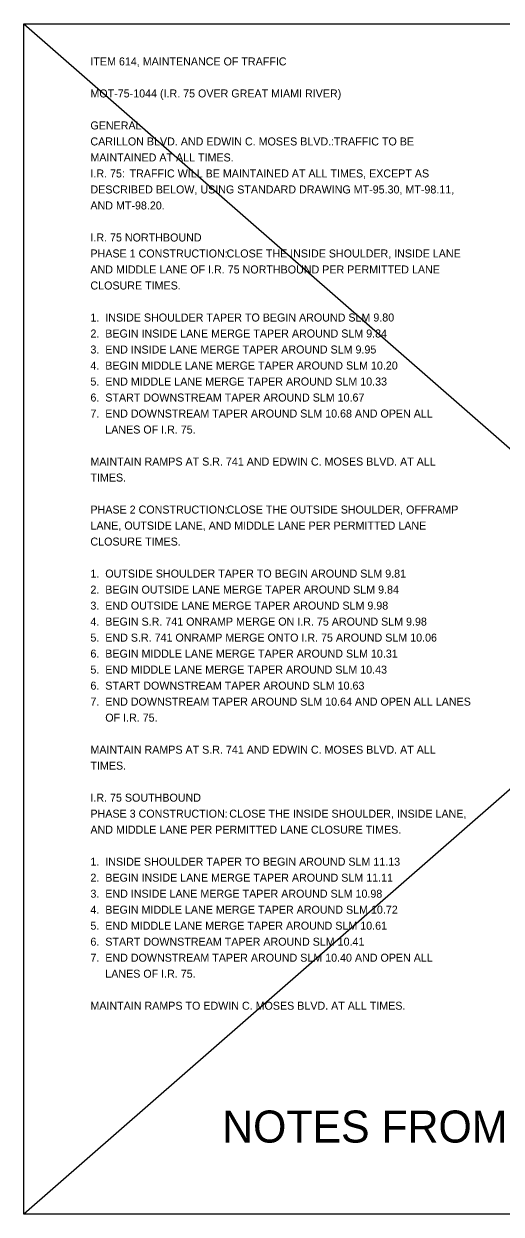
# Model space of a CAD drawing. Extents: x -25.5 to 52.6, y -2.3 to 22.
# Drawn here: x -25.52 to -17.16, y 0.89 to 21.72 of the extents above; entities that cross this region are included whole.
import ezdxf

# ---------------------------------------------------------------- set-up
doc = ezdxf.new("R2010")
doc.units = 0
doc.layers.add('Default', color=7, linetype='Continuous')
doc.layers.add('SH_Text', color=7, linetype='Continuous')

msp = doc.modelspace()

# ---------------------------------------------------------------- linework, layer by layer
at = {"layer": 'Default'}
msp.add_lwpolyline([(-25.517, 21.716), (-1.676, 21.716), (-1.676, 0.891), (-25.517, 0.891)], close=True, dxfattribs=at)
at = {"layer": 'SH_Text'}
for p, q in [((-25.517, 21.716), (-1.676, 0.891)), ((-1.676, 21.716), (-25.517, 0.891))]:
    msp.add_line(p, q, dxfattribs=at)

# ---------------------------------------------------------------- texts
for s, height, p in [('ITEM 614, MAINTENANCE OF TRAFFIC', 0.14, (-24.351, 20.988)), ('MOT-75-1044 (I.R. 75 OVER GREAT MIAMI RIVER)', 0.14, (-24.351, 20.428)), ('GENERAL', 0.14, (-24.351, 19.868)), ('CARILLON BLVD. AND EDWIN C. MOSES BLVD.: ', 0.14, (-24.351, 19.588)), ('TRAFFIC TO BE ', 0.14, (-20.091, 19.588)), ('MAINTAINED AT ALL TIMES.', 0.14, (-24.351, 19.308)), ('I.R. 75: ', 0.14, (-24.351, 19.028)), ('TRAFFIC WILL BE MAINTAINED AT ALL TIMES, EXCEPT AS ', 0.14, (-23.666, 19.028)), ('DESCRIBED BELOW, USING STANDARD DRAWING MT-95.30, MT-98.11, ', 0.14, (-24.351, 18.748)), ('AND MT-98.20.', 0.14, (-24.351, 18.468)), ('I.R. 75 NORTHBOUND', 0.14, (-24.351, 17.908)), ('PHASE 1 CONSTRUCTION:', 0.14, (-24.351, 17.628)), (' CLOSE THE INSIDE SHOULDER, INSIDE LANE ', 0.14, (-22.02, 17.628)), ('AND MIDDLE LANE OF I.R. 75 NORTHBOUND PER PERMITTED LANE ', 0.14, (-24.351, 17.348)), ('CLOSURE TIMES.', 0.14, (-24.351, 17.068)), ('1.  INSIDE SHOULDER TAPER TO BEGIN AROUND SLM 9.80', 0.14, (-24.351, 16.508)), ('2.  BEGIN INSIDE LANE MERGE TAPER AROUND SLM 9.84', 0.14, (-24.351, 16.228)), ('3.  END INSIDE LANE MERGE TAPER AROUND SLM 9.95', 0.14, (-24.351, 15.948)), ('4.  BEGIN MIDDLE LANE MERGE TAPER AROUND SLM 10.20', 0.14, (-24.351, 15.668)), ('5.  END MIDDLE LANE MERGE TAPER AROUND SLM 10.33', 0.14, (-24.351, 15.388)), ('6.  START DOWNSTREAM TAPER AROUND SLM 10.67', 0.14, (-24.351, 15.108)), ('7.  END DOWNSTREAM TAPER AROUND SLM 10.68 AND OPEN ALL', 0.14, (-24.351, 14.828)), ('     LANES OF I.R. 75.', 0.14, (-24.351, 14.548)), ('MAINTAIN RAMPS AT S.R. 741 AND EDWIN C. MOSES BLVD. AT ALL ', 0.14, (-24.351, 13.988)), ('TIMES.', 0.14, (-24.351, 13.708)), ('PHASE 2 CONSTRUCTION:', 0.14, (-24.351, 13.148)), (' CLOSE THE OUTSIDE SHOULDER, OFFRAMP ', 0.14, (-22.02, 13.148)), ('LANE, OUTSIDE LANE, AND MIDDLE LANE PER PERMITTED LANE ', 0.14, (-24.351, 12.868)), ('CLOSURE TIMES.', 0.14, (-24.351, 12.588)), ('1.  OUTSIDE SHOULDER TAPER TO BEGIN AROUND SLM 9.81', 0.14, (-24.351, 12.028)), ('2.  BEGIN OUTSIDE LANE MERGE TAPER AROUND SLM 9.84', 0.14, (-24.351, 11.748)), ('3.  END OUTSIDE LANE MERGE TAPER AROUND SLM 9.98', 0.14, (-24.351, 11.468)), ('4.  BEGIN S.R. 741 ONRAMP MERGE ON I.R. 75 AROUND SLM 9.98', 0.14, (-24.351, 11.188)), ('5.  END S.R. 741 ONRAMP MERGE ONTO I.R. 75 AROUND SLM 10.06', 0.14, (-24.351, 10.908)), ('6.  BEGIN MIDDLE LANE MERGE TAPER AROUND SLM 10.31', 0.14, (-24.351, 10.628)), ('5.  END MIDDLE LANE MERGE TAPER AROUND SLM 10.43', 0.14, (-24.351, 10.348)), ('6.  START DOWNSTREAM TAPER AROUND SLM 10.63', 0.14, (-24.351, 10.068)), ('7.  END DOWNSTREAM TAPER AROUND SLM 10.64 AND OPEN ALL LANES', 0.14, (-24.351, 9.788)), ('     OF I.R. 75.', 0.14, (-24.351, 9.508)), ('MAINTAIN RAMPS AT S.R. 741 AND EDWIN C. MOSES BLVD. AT ALL ', 0.14, (-24.351, 8.948)), ('TIMES.', 0.14, (-24.351, 8.668)), ('I.R. 75 SOUTHBOUND', 0.14, (-24.351, 8.108)), ('PHASE 3 CONSTRUCTION:  ', 0.14, (-24.351, 7.828)), ('CLOSE THE INSIDE SHOULDER, INSIDE LANE, ', 0.14, (-21.921, 7.828)), ('AND MIDDLE LANE PER PERMITTED LANE CLOSURE TIMES.', 0.14, (-24.351, 7.548)), ('1.  INSIDE SHOULDER TAPER TO BEGIN AROUND SLM 11.13', 0.14, (-24.351, 6.988)), ('2.  BEGIN INSIDE LANE MERGE TAPER AROUND SLM 11.11', 0.14, (-24.351, 6.708)), ('3.  END INSIDE LANE MERGE TAPER AROUND SLM 10.98', 0.14, (-24.351, 6.428)), ('4.  BEGIN MIDDLE LANE MERGE TAPER AROUND SLM 10.72', 0.14, (-24.351, 6.148)), ('5.  END MIDDLE LANE MERGE TAPER AROUND SLM 10.61', 0.14, (-24.351, 5.868)), ('6.  START DOWNSTREAM TAPER AROUND SLM 10.41', 0.14, (-24.351, 5.588)), ('7.  END DOWNSTREAM TAPER AROUND SLM 10.40 AND OPEN ALL', 0.14, (-24.351, 5.308)), ('     LANES OF I.R. 75.', 0.14, (-24.351, 5.028)), ('MAINTAIN RAMPS TO EDWIN C. MOSES BLVD. AT ALL TIMES.', 0.14, (-24.351, 4.468)), ('NOTES FROM THE STAGE 1 SUBMISSION', 0.56, (-22.045, 2.144))]:
    msp.add_text(s, height=height, dxfattribs=at).set_placement(p)

doc.saveas('drawing.dxf')
